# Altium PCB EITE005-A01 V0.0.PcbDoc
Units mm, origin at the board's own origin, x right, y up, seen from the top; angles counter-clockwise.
Board outline 14.16 x 11.86 mm, 4 copper layers (TopLayer, Signal Layer 1, Signal Layer 2, BottomLayer), stack 0.7 mm thick; 45 components, 30 nets, 145 pads, 56 vias.
Unrouted connection lines stored in the file: 1.
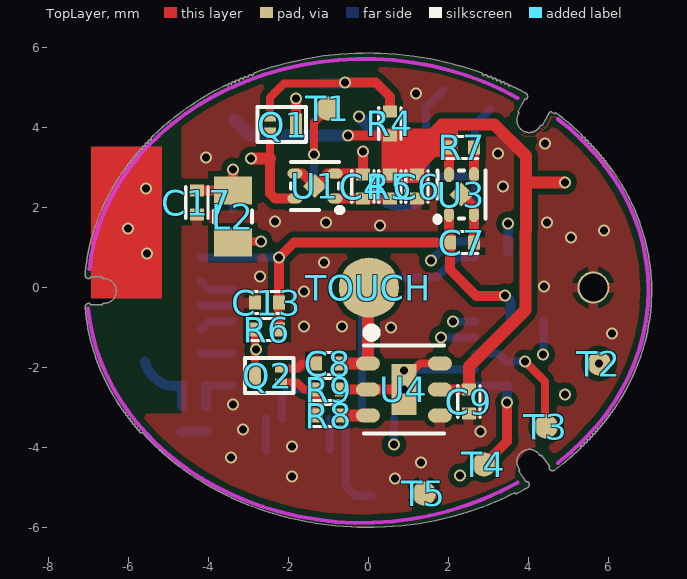
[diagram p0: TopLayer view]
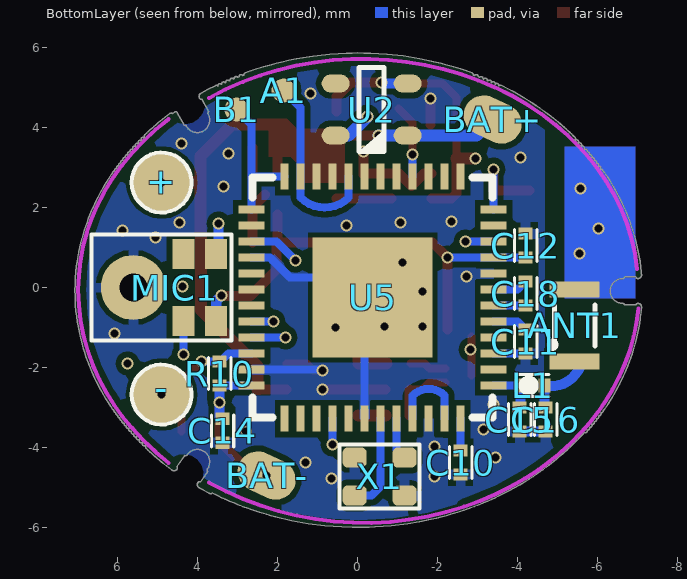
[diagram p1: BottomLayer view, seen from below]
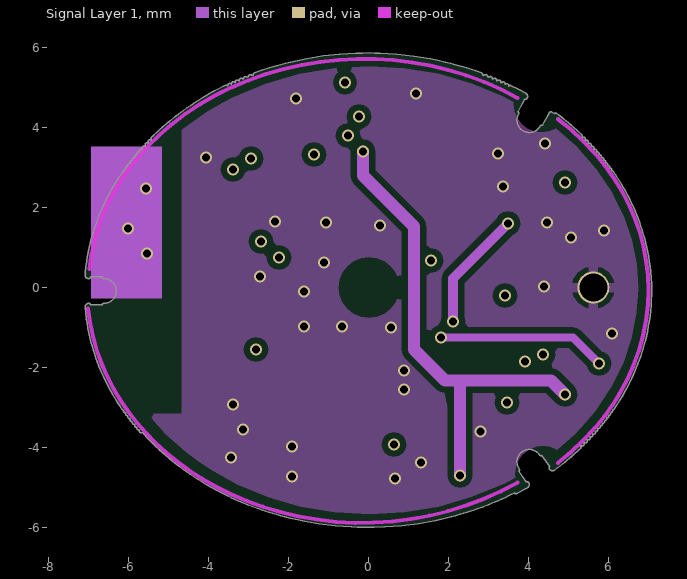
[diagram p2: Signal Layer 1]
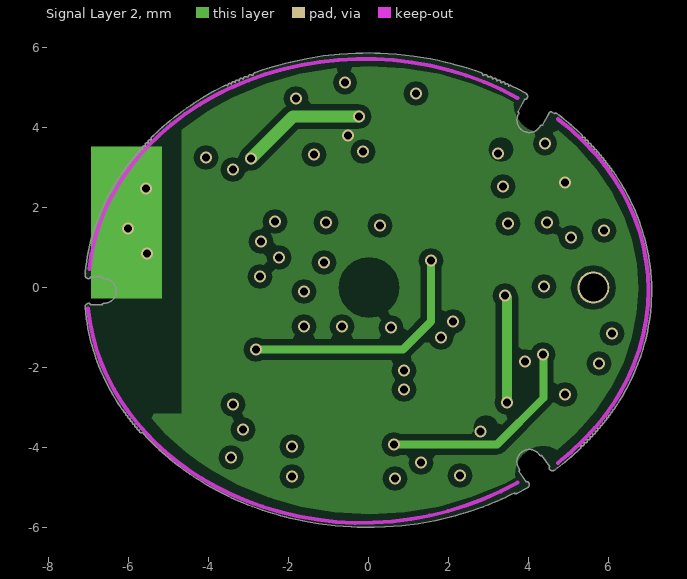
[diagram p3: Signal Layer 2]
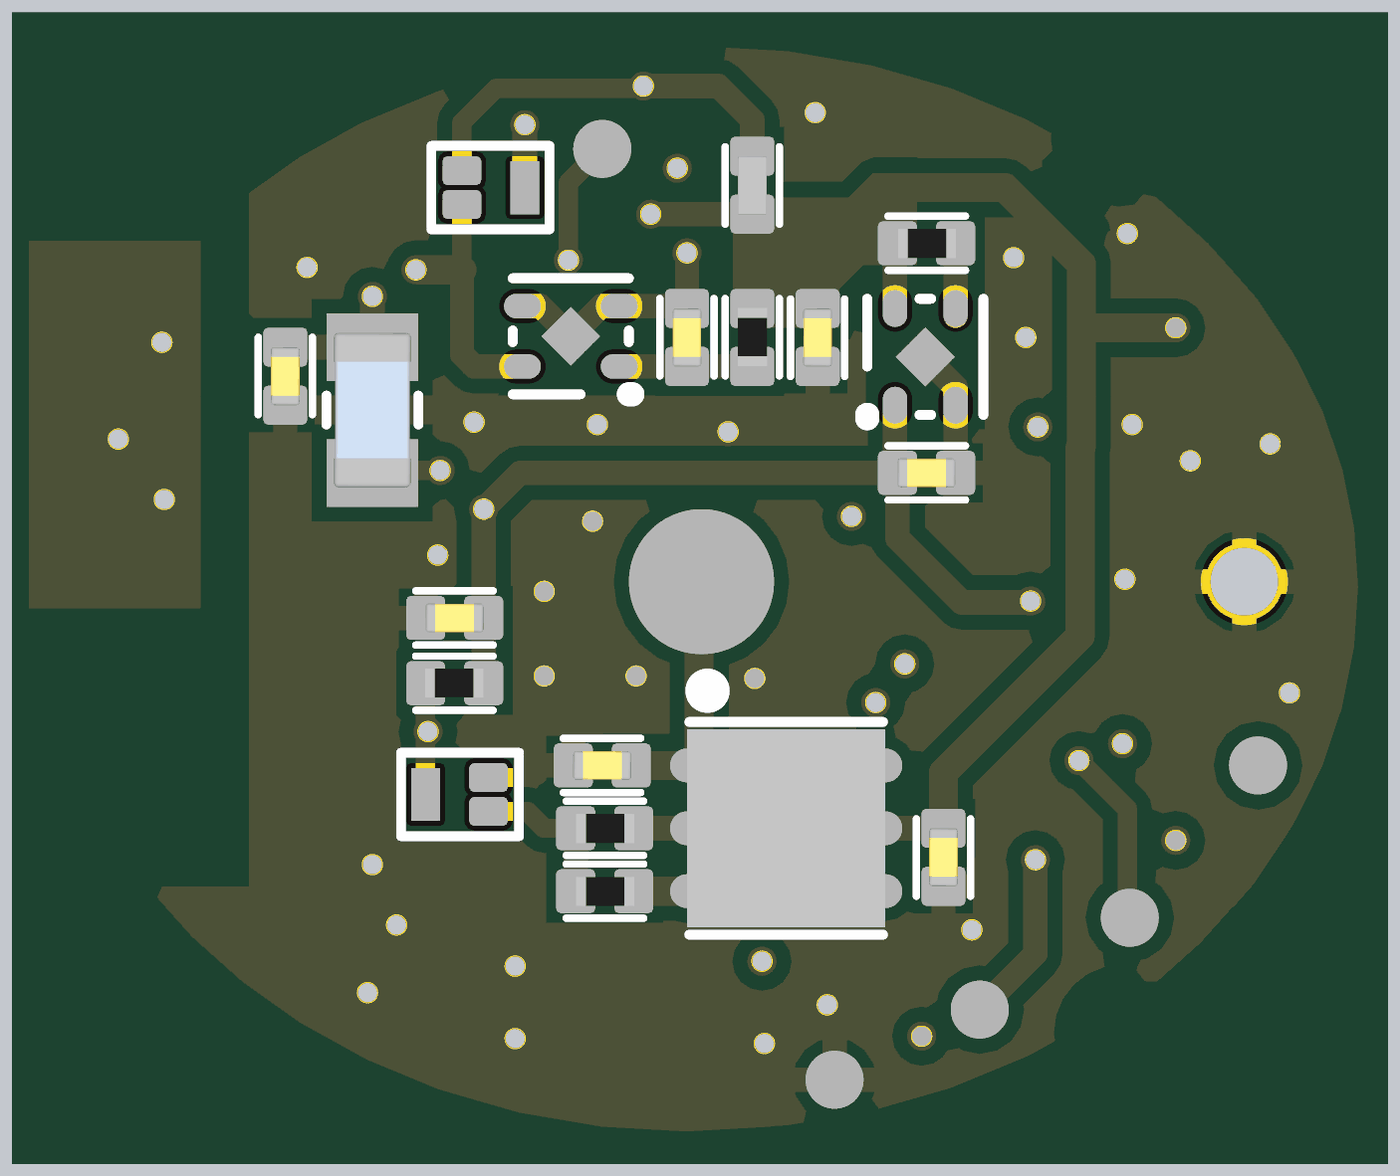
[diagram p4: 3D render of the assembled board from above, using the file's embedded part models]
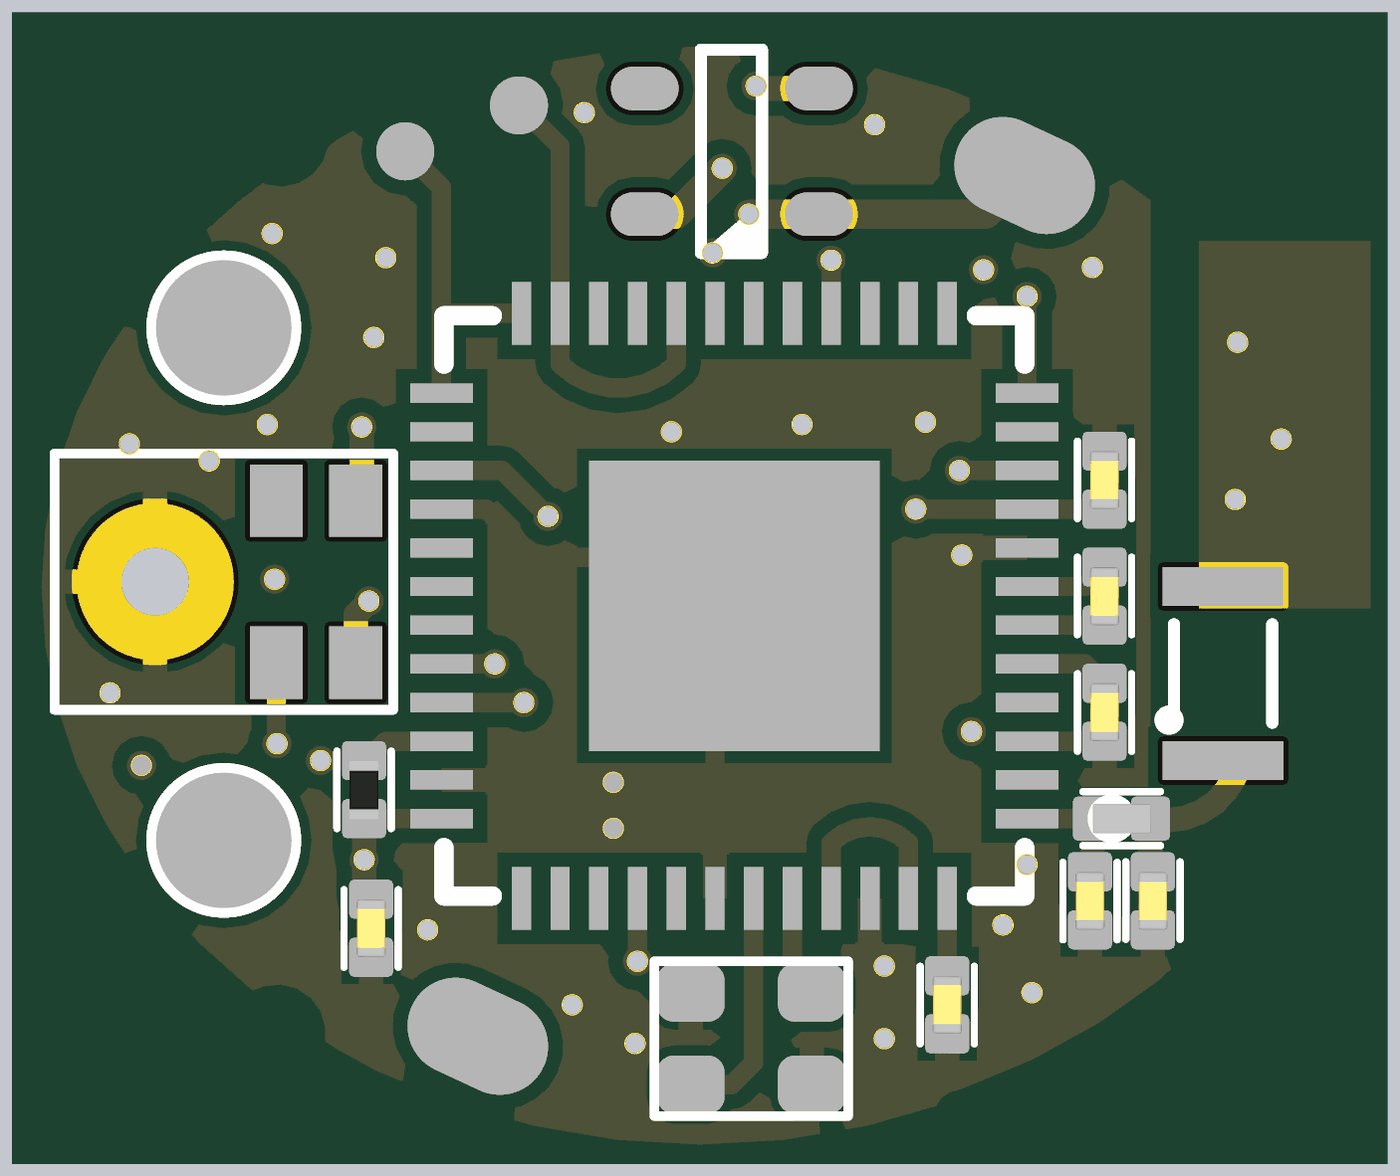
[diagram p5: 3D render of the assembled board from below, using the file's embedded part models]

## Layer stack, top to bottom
TopSolder: solder mask 0.05, Solder Resist, Dk 3.5
TopLayer: signal copper 0.05
Dielectric1: core 0.147, FR-4, Dk 4.2
Signal Layer 1: signal copper 0.036
Dielectric 3: prepreg 0.127, Dk 4.2
Signal Layer 2: signal copper 0.036
Dielectric 2: core 0.254, Dk 4.2
BottomLayer: signal copper 0.05
BottomSolder: solder mask 0.05, Solder Resist, Dk 3.5

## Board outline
799 vertices, not listed, extent -7.098,-5.996 7.067,5.863

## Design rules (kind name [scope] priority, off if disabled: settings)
Clearance [All] p1: gap=0.15 ignorepadtopadclearanceinfootprint=FALSE except(0: Arc-Hole Track-Hole SMDPad-Hole THPad-Hole Via-Hole Fill-Hole Poly-Hole Region-Hole Text-Hole)
FabricationTestPointUsage TestPointUsage [All] p1: valid=0 allowmultiple=FALSE
FabricationTestpoint Testpoint [All] p1: side=3 testpointundercomponent=TRUE minsize=1.016 maxsize=2.54 preferedsize=1.524 minholesize=0.508 maxholesize=1.016 preferedholesize=0.813 testpointgrid=0.025 allowsidetop=TRUE allowsidebottom=TRUE usegrid=TRUE gridtolerance=0
PlaneClearance [All] p1: clearance=0.127
PolygonConnect PolygonConnect_1 [IsVia] p1: connectstyle=Direct reliefconductorwidth=0.254 reliefentries=4 polygonreliefangle="90 Angle" airgapwidth=0.254
PolygonConnect [All vs (InPadClass('All Pads'))] p2: connectstyle=Relief reliefconductorwidth=0.25 reliefentries=4 polygonreliefangle="90 Angle" airgapwidth=0.127
RoutingVias [All] p1: holewidth=0.711 width=1.27 viastyle="Through Hole" minholewidth=0.1 minwidth=1.27 maxholewidth=0.711 maxwidth=1.27
SilkToSolderMaskClearance SilkscreenOverComponentPads [IsPad] p1: minsilkscreentomaskgap=0.254 clearancetoexposedcopper=TRUE
SolderMaskExpansion [All] p1: expansion=0
Width [All] p1: maxlimit=2 minlimit=0.1 preferedwidth=0.254 toplayer_prefwidth=0.15 bottomlayer_prefwidth=0.15 minimp=50.000000 maximp=50.000000 favimp=50.000000
26 further rules are at their usual default settings.

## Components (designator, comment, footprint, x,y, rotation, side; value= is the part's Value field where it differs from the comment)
+ "" PAD_1#1 5.1,2.825 r180 bottom locked
- "" PAD_1#2 4.9,-2.675 r180 bottom
A1 "PAD" PAD0608 1.85,4.925 r180 bottom
ANT1 "ANT_SMD" ANT2012_2.4G_1 -5.425,-0.95 r90 bottom
B1 "PAD" PAD0608 3.025,4.45 r180 bottom
BAT+ "" PAD_1#3 -3.375,4.2 r0 bottom
BAT- "" PAD_1#3 2.275,-4.7 r0 bottom
C4 "100nF" 0201-C -0.15,2.525 r90 top
C6 "4.7uF" 0201-C 1.2,2.525 r270 top
C7 "4.7uF" 0201-C 2.325,1.125 r0 top
C8 "1-50pF" 0201-C -1.025,-1.9 r180 top
C9 "0.1uF" 0201-C 2.5,-2.85 r270 top
C10 "2.2uF" 0201-C -2.575,-4.375 r270 bottom
C11 "1uF" 0201-C -4.2,-1.35 r270 bottom
C12 "4.7uF" 0201-C -4.2,1.05 r90 bottom
C13 "100pF" 0201-C -2.55,-0.375 r180 top
C14 "1uF" 0201-C 3.377,-3.583 r270 bottom
C15 "1pF" 0201-C -4.05,-3.3 r270 bottom
C16 "1pF" 0201-C -4.7,-3.3 r90 bottom
C17 "4.7uF" 0201-C -4.3,2.125 r90 top
C18 "1uF" 0201-C -4.2,-0.15 r90 bottom
L1 "2.2uH" 0201 -4.075,-2.45 r180 bottom
L2 "2.2uH" L_0603 -3.4,1.775 r270 top
MIC1 "SPH0641LM4H-1" SPH0641LM4H-1 5.609,0 r270 bottom locked
Q1 "RV2C002UN" DFN1006 -1.825,4.075 r270 top
Q2 "RV2C002UN" DFN1006 -2.85,-2.2 r90 top
R4 "470K" 0201 0.525,4.4 r270 top
R5 "100R" 0201-R 0.525,2.525 r90 top
R6 "100K" 0201-R -2.55,-1.05 r180 top
R7 "10K" 0201-R 2.325,3.5 r0 top
R8 "100K" 0201-R -1,-3.2 r0 top
R9 "100K" 0201-R -1,-2.55 r0 top
R10 "100K" 0201-R 3.45,-2.15 r270 bottom
T1 "" PAD06 -1.025,4.475 r0 top
T2 "" PAD06 5.75,-1.9 r270 top
T3 "" PAD06 4.425,-3.475 r270 top
T4 "" PAD06 2.875,-4.425 r270 top
T5 "" PAD06 1.375,-5.15 r270 top
TOUCH "" PAD_1#2 0,0 r90 top
U1 "XB6042Q2SV" UTDFN-4L_1 -0.85,2.225 r90 top
U2 "MRX1518H" SON-4 -0.35,4.45 r90 bottom
U3 "SGM2036-1V3" UTDFN-4L_1 2,1.825 r0 top
U4 "TTP233D" DNF-6 0.875,-2.55 r0 top
U5 "RSL10" "QFN-48 RSL10" -0.375,-0.25 r0 bottom locked
X1 "48MHZ" SMDP4P_2016 -0.55,-4.725 r180 bottom

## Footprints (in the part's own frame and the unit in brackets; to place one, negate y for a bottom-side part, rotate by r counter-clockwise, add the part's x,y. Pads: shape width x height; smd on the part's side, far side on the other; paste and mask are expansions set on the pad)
0201 [mil]
  rect 12x14 smd paste+1.97 mask+1.97: 1(0,0) 2(23.62,0)
  silkscreen extent -4,-11 28,11, body extent 0,-6 24,6, height 12
0201-C [mil]
  rect 12x14 smd paste+1.97 mask+1.97: 1(-11.81,0) 2(11.81,0)
  silkscreen extent -16,-11 16,11, body extent -12,-6 12,6, height 12
0201-R [mil]
  rect 12x14 smd paste+1.97 mask+1.97: 1(-11.81,0) 2(11.81,0)
  silkscreen extent -16,-11 16,11, body extent -12,-6 12,6, height 7
ANT2012_2.4G_1 [mm]
  rect 0.4x1.25 smd mask+0.05: 1(-0.9,0) 2(0.9,0)
  silkscreen extent -0.51,-0.51 0.51,0.56
DFN1006 [mm]
  rect 0.55x0.3 smd paste+0 mask+0.05: D(0,0)
  rect 0.2x0.3 smd paste+0.05 mask+0.1: G(-0.175,-0.65) S(0.175,-0.65)
  silkscreen extent -0.43,-0.97 0.43,0.25
DNF-6 [mm]
  oval 0.6x0.35 smd: 1(-0.9,0.65) 2(-0.9,0) 3(-0.9,-0.65) 4(0.9,-0.65) 5(0.9,0) 6(0.9,0.65)
  rect 0.635x1.27 smd: 7(0,0)
  silkscreen extent -1,-1.1 1,1.52, body extent -1.02,-1.03 1.03,1.02, height 0.8
L_0603 [mm]
  rect 0.7x0.95 smd: 1(-0.65,0) 2(0.65,0)
  silkscreen extent -0.15,-0.48 0.15,0.48, body extent -0.8,-0.4 0.8,0.4, height 0.8
PAD06 [mm]
  round 0.6 smd: 0(0,0)
PAD0608 [mm]
  round 0.6 smd: 0(0,0)
PAD_1#1 [mm]
  round 1.5 smd: 0(0.2,-0.2)
PAD_1#2 [mm]
  round 1.5 smd: 0(0,0)
PAD_1#3 [mm]
  oval 1.5x1 smd rot 155: 0(0,0)
"QFN-48 RSL10" [mm]
  rect 0.65x0.2 smd: 1(-3.025,2.2) 2(-3.025,1.8) 3(-3.025,1.4) 4(-3.025,1) 5(-3.025,0.6) 6(-3.025,0.2) 7(-3.025,-0.2) 8(-3.025,-0.6) 9(-3.025,-1) 10(-3.025,-1.4) 11(-3.025,-1.8) 12(-3.025,-2.2) 25(3.025,-2.2) 26(3.025,-1.8) 27(3.025,-1.4) 28(3.025,-1) 29(3.025,-0.6) 30(3.025,-0.2) 31(3.025,0.2) 32(3.025,0.6) 33(3.025,1) 34(3.025,1.4) 35(3.025,1.8) 36(3.025,2.2)
  rect 0.2x0.65 smd: 13(-2.2,-3.025) 14(-1.8,-3.025) 15(-1.4,-3.025) 16(-1,-3.025) 17(-0.6,-3.025) 18(-0.2,-3.025) 19(0.2,-3.025) 20(0.6,-3.025) 21(1,-3.025) 22(1.4,-3.025) 23(1.8,-3.025) 24(2.2,-3.025) 37(2.2,3.025) 38(1.8,3.025) 39(1.4,3.025) 40(1,3.025) 41(0.6,3.025) 42(0.2,3.025) 43(-0.2,3.025) 44(-0.6,3.025) 45(-1,3.025) 46(-1.4,3.025) 47(-1.8,3.025) 48(-2.2,3.025)
  rect 3x3 smd: 49(0,0)
  silkscreen extent -4.02,-3 3,3, body extent -3,-3 3,3, height 1
SMDP4P_2016 [mm]
  rrect50% 0.6x0.5 smd paste+0.05: 1(-0.625,-0.475) 2(0.625,-0.475) 3(0.625,0.475) 4(-0.625,0.475)
  silkscreen extent -1,-0.8 1,0.8
SON-4 [mm]
  oval 0.45x0.7 smd mask+0.051: 1(-0.65,-0.9) 2(0.65,-0.9) 3(0.65,0.9) 4(-0.65,0.9)
  silkscreen extent -1.05,-0.31 1.05,0.32
SPH0641LM4H-1 [mm]
  rect 0.75x0.55 smd mask+0.05: 1(-0.837,2.074) 2(-0.838,1.252) 4(0.838,1.252) 5(0.837,2.074)
  round 1.625 / inner round 0.8 / far side round 0.8 hole 0.7 mask+0.05: 3(0,0)
  silkscreen extent -1.33,-1.04 1.33,2.46
UTDFN-4L_1 [mil]
  oval 10x15 smd mask+1.97: 1(0,0) 2(24.61,0) 3(24.61,39.37) 4(0,39.37)
  rect 17x17 smd rot 45: 5(12.3,19.69)
  silkscreen extent -11,-5 36,43

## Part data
+ - BAT+ BAT- T1 T2 T3 T4 T5 TOUCH: library part PAD
C4 C6 C7 C8 C9 C10 C11 C12 C13 C14 C15 C16 C17 C18: library part CAP, "Capacitor"
L1 L2: library part L
MIC1: library part MIC
Q1 Q2: library part MOS-N
R4 R5 R6 R7 R8 R9 R10: library part Res1, "Resistor"
U1: library part XB6042
U3: library part SGM2036
U5: "RSL10 QFN-48"
X1: library part XT

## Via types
v1: diameter 0.3, hole 0.2, TopLayer to BottomLayer, tented both sides, 56 vias

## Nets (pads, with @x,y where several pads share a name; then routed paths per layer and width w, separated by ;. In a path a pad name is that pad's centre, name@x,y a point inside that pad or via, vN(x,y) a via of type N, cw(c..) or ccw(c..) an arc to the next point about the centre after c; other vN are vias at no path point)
1V85: C7.1 C12.1 C13.1 C14.1 MIC1.5 R6.1 R10.2 T4.0 U3.1 U5.9 U5.36 | length 18
  TopLayer w0.25: R6.1 C13.1 v1(-2.25,0.75) -1.875,1.125 C7.1@2,1.125 ; U3.1 C7.1@2,1.125 ; C7.1 C7.1@2,1.125 ; T4.0 3.45,-3.85 v1(3.45,-2.875)
  TopLayer w0.254: C7.1 2.025,0.45 2.69,-0.215 v1@3.425,-0.215
  Signal Layer 2 w0.254: v1(3.4,-0.2) 3.45,-0.25 v1(3.45,-2.875)
  BottomLayer w0.2: C12.1 U5.9 v1(-2.25,0.75) ; U5.36 R10.2
  BottomLayer w0.254: v1(3.4,-0.2) 3.535,-0.335 MIC1.5 ; C14.1@3.45,-3.275 v1(3.45,-2.875) R10.2
AGND: Q1.S U1.4 U2.4 | length 6.8
  TopLayer w0.2: -2.475,3.225 Q1.S
  TopLayer w0.25: -2.475,3.225 -2.475,2.35 -2.35,2.225 U1.4
  TopLayer w0.3: v1(-2.95,3.225) -2.475,3.225
  Signal Layer 2 w0.3: v1(-2.95,3.225) -1.9,4.275 v1(-0.25,4.275)
  BottomLayer w0.3: v1(-0.25,4.275) 0.225,3.8 U2.4
GND: ANT1.2 C6.2 C7.2 C8.2 C9.2 C10.2 C11.2 C12.2 C13.2 C14.2 C15.2 C16.1 C17.1 MIC1.3 Q1.D Q2.S R9.2 T5.0 U3.2 U3.5 U4.2 U4.4 U4.6 U5.3 U5.8 U5.28 U5.35 U5.42 U5.46 U5.49 X1.2 X1.4 | length 14.9
  TopLayer w0.2: Q2.S -1.8,-2.025 -1.7,-1.925 -1.675,-1.9 C8.2 ; v1(0.875,-2.075) 1.1,-2.075 1.275,-1.9 U4.6
  TopLayer w0.254: Q1.D v1(-1.825,4.725) ; R9.2 U4.2 v1(0.875,-2.55) ; U3.5 2.625,2.013 U3.2 C7.2
  BottomLayer w0.2: C11.2 U5.3 ; U5.49 0.125,0.25 1.691,0.25 2.191,0.75 U5.28 ; U5.42 U5.49@-0.175,-0.45 ; v1@0.9,-2.05 U5.35
  BottomLayer w0.254: C16.1 C15.2
  other v1: 0.65,-4.775 -1.925,-4.725 1.3,-4.375 -3.45,-4.25 -1.925,-3.975 2.793,-3.6 -3.15,-3.55 -3.4,-2.925 6.075,-1.15 0.55,-1 -1.625,-0.975 -0.675,-0.975 -1.625,-0.1 4.375,0.025 -2.725,0.275 -1.125,0.625 5.05,1.25 5.875,1.425 0.275,1.55 -1.075,1.625 4.45,1.625 -2.35,1.65 3.35,2.525 -4.075,3.25 3.225,3.35 4.4,3.6 1.175,4.85
JTCK: T2.0 U5.33 | length 5.1
  Signal Layer 1 w0.2: v1(1.8,-1.25) 5.1,-1.25 v1(5.75,-1.9)
  BottomLayer w0.2: v1(1.8,-1.25) U5.33
JTMS: R10.1 T3.0 U5.34 | length 3.3
  TopLayer w0.2: v1(3.9,-1.85) 4.4,-2.35 T3.0@4.4,-3.6
  BottomLayer w0.2: U5.34 3.225,-1.65 3.425,-1.85 R10.1 v1(3.9,-1.85)
KEY: Q2.D R6.2 U5.27 | length 8.5
  TopLayer w0.2: Q2.D R6.2@-2.85,-1.225
  Signal Layer 2 w0.2: v1(-2.825,-1.55) 0.85,-1.55 1.55,-0.85 v1(1.55,0.675)
  BottomLayer w0.2: v1(1.55,0.675) 2.025,1.15 U5.27
MIC_CLK: MIC1.4 U5.40 | length 6.8
  Signal Layer 2 w0.2: v1(0.625,-3.925) 3.2,-3.925 4.357,-2.768 v1@4.357,-1.675
  BottomLayer w0.2: v1(0.625,-3.925) U5.40 ; v1@4.357,-1.675 MIC1.4
  other v1: 4.35,-1.675
MIC_DATA: MIC1.1 U5.32 | length 4.3
  Signal Layer 1 w0.254: v1(2.1,-0.85) 2.1,0.225 v1(3.475,1.6)
  BottomLayer w0.2: v1(2.1,-0.85) U5.32
  BottomLayer w0.254: MIC1.1@3.475,0.898 v1(3.475,1.6)
Net-_0: -.0 BAT-.0 C4.2 U1.2 U1.3 U1.5 | length 14.6
  TopLayer w0.25: U1.3 -1.662,2.85 U1.5 -1.038,2.85 U1.2 C4.2@-0.175,2.85 ; C4.2 v1(-0.15,3.4)
  Signal Layer 1 w0.3: v1(-0.15,3.4) -0.15,2.8 1.125,1.525 1.125,-1.55 1.9,-2.325 2.275,-2.325 ; v1(2.275,-4.7) 2.275,-2.325 ; v1(4.9,-2.675) 4.55,-2.325 2.275,-2.325
NetANT1_1: ANT1.1 C16.2 L1.2 | length 1.7
  BottomLayer w0.254: ANT1.1@-5.6,-1.85 ccw(c-4.84,-1.69) L1.2@-4.68,-2.45 ; C16.2@-4.675,-2.975 L1.2
NetC4_1: C4.1 R5.1 U1.1 | length 1.4
  TopLayer w0.25: U1.1 C4.1
  TopLayer w0.254: C4.1 R5.1
NetC8_1: C8.1 TOUCH.0 U4.1 | length 2.6
  TopLayer w0.3: C8.1 U4.1 TOUCH.0@-0.025,-0.025
NetC10_1: C10.1 U5.48 | length 0.8
  BottomLayer w0.2: C10.1 U5.48
NetC15_1: C15.1 L1.1 U5.1 | length 1.2
  BottomLayer w0.2: L1.1 U5.1
  BottomLayer w0.254: C15.1@-4.075,-2.975 L1.1
NetC17_2: C17.2 L2.1 U5.12 | length 2.4
  TopLayer w0.254: C17.2 L2.1 v1(-3.4,2.95)
  BottomLayer w0.2: U5.12 v1(-3.4,2.95)
NetC18_1: C18.1 U5.6 | length 0.8
  BottomLayer w0.2: C18.1 U5.6
NetC18_2: C18.2 U5.7 | length 0.9
  BottomLayer w0.2: C18.2 -4,-0.05 U5.7
NetL2_2: L2.2 U5.10 | length 1.4
  TopLayer w0.2: L2.2@-3.375,1.15 v1(-2.7,1.15)
  BottomLayer w0.2: U5.10 v1(-2.7,1.15)
NetQ1_G: Q1.G R4.1 U2.2 | length 4.8
  TopLayer w0.2: Q1.G -2.475,4.75 -2.125,5.1 -0.625,5.1 v1(-0.6,5.125)
  TopLayer w0.254: v1(-0.6,5.125) 0.175,5.125 0.525,4.775 R4.1
  BottomLayer w0.254: U2.2 -0.625,5.1 v1(-0.6,5.125)
NetQ2_G: Q2.G R8.1 R9.1 | length 1.6
  TopLayer w0.2: Q2.G -1.8,-2.375 -1.625,-2.55 R9.1
  TopLayer w0.254: R8.1 R9.1
NetR7_2: R7.2 U3.3 | length 0.8
  TopLayer w0.25: U3.3@2.625,2.75 U3.3 R7.2
NetR8_2: R8.2 U4.3 | length 0.7
  TopLayer w0.3: R8.2 U4.3
NetU5_45: U5.45 U5.47 | length 2
  BottomLayer w0.2: U5.47 -2.175,-2.7 cw(c-1.775,-3.1) -1.375,-2.7 U5.45
NRST: T1.0 U5.16 | length 1.8
  TopLayer w0.2: v1(-1.375,3.325) -1.375,4.125 T1.0
  BottomLayer w0.2: U5.16 v1(-1.375,3.325)
SPEAKER+: A1.0 U5.20 U5.23 | length 4.7
  BottomLayer w0.2: U5.20 0.225,2.25 ccw(c0.825,2.85) 1.425,2.25 U5.23 1.425,4.5 A1.0
SPEAKER-: B1.0 U5.24 U5.25 | length 3.5
  BottomLayer w0.2: U5.24 2.65,2.775 ; U5.25 2.65,2.775 ; B1.0 2.65,4.075 2.65,2.775
VCC: +.0 BAT+.0 C6.1 C9.1 R4.2 R5.2 R7.1 U2.1 U3.4 U4.5 | length 15.6
  TopLayer w0.25: U3.4 R7.1@2,3.5 ; R7.1 R7.1@2.025,3.525
  TopLayer w0.254: v1(-0.525,3.8) R4.2 ; U4.5 C9.1
  TopLayer w0.3: R5.2 C6.1 ; 2.223,4.075 3.136,4.075 3.925,3.286 3.925,2.625 ; C9.1 2.5,-1.975 3.912,-0.563 3.912,1.388 3.925,1.401 3.925,2.625 ; v1(4.9,2.625) 3.925,2.625
  BottomLayer w0.3: BAT+.0 -2.975,3.8 U2.1 v1(-0.525,3.8)
VDDA: C11.1 U5.5 | length 0.9
  BottomLayer w0.2: C11.1 -4,-0.85 U5.5
XTAL48N: U5.43 X1.1 | length 2.4
  BottomLayer w0.2: U5.43 -0.575,-4.975 -0.35,-5.2 X1.1
XTAL48P: U5.44 X1.3 | length 0.8
  BottomLayer w0.2: X1.3@-0.975,-4.05 U5.44
pads on no net: MIC1.2 U2.3 U4.7 U5.2 U5.4 U5.11 U5.13 U5.14 U5.15 U5.17 U5.18 U5.19 U5.21 U5.22 U5.26 U5.29 U5.30 U5.31 U5.37 U5.38 U5.39 U5.41
copper on no net:
  other v1: -5.55,0.85 -6.025,1.475 -5.575,2.475

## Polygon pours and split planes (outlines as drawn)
GND on Signal Layer 1 "Top Layer-No Net" (solid, remove dead copper, pour order 6): -6.202,-2.528 cw(c-1.704,0.024) -6.848,-0.507 ccw(c-6.923,-0.012) -6.861,0.484 cw(c-1.886,-0.046) -6.298,2.313 cw(c-1.359,-0.342) -5.657,3.26 cw(c-0.89,-0.734) -4.819,4.087 cw(c-0.467,-1.256) -3.725,4.816 cw(c0.01,-2.311) 2.105,5.458 cw(c0.153,-1.851) 3.843,4.753 ccw(c4.315,4.585) 4.674,4.237 cw(c0.862,-0.788) 5.581,3.396 cw(c1.343,-0.366) 6.288,2.404 cw(c1.97,-0.043) 6.932,-0.023 cw(c1.803,-0.003) 6.218,-2.614 cw(c1.274,0.265) 5.62,-3.456 cw(c0.823,0.65) 4.709,-4.327 4.704,-4.315 ccw(c4.347,-4.665) 3.888,-4.863 cw(c0.017,2.075) -2.487,-5.465 cw(c-0.206,1.444) -4.348,-4.538 cw(c-0.671,0.762) -5.402,-3.623 cw(c-1.154,0.32)
VCC on Signal Layer 2 "Top Layer-No Net" (solid, remove dead copper, pour order 5): -6.202,-2.528 cw(c-1.704,0.024) -6.848,-0.507 ccw(c-6.923,-0.012) -6.861,0.484 cw(c-1.886,-0.046) -6.298,2.313 cw(c-1.359,-0.342) -5.657,3.26 cw(c-0.89,-0.734) -4.819,4.087 cw(c-0.467,-1.256) -3.725,4.816 cw(c0.01,-2.311) 2.105,5.458 cw(c0.153,-1.851) 3.843,4.753 ccw(c4.315,4.585) 4.674,4.237 cw(c0.862,-0.788) 5.581,3.396 cw(c1.343,-0.366) 6.288,2.404 cw(c1.97,-0.043) 6.932,-0.023 cw(c1.803,-0.003) 6.218,-2.614 cw(c1.274,0.265) 5.62,-3.456 cw(c0.823,0.65) 4.709,-4.327 4.704,-4.315 ccw(c4.347,-4.665) 3.888,-4.863 cw(c0.017,2.075) -2.487,-5.465 cw(c-0.206,1.444) -4.348,-4.538 cw(c-0.671,0.762) -5.402,-3.623 cw(c-1.154,0.32)
GND on BottomLayer "Top Layer-No Net" (solid, remove dead copper, pour order 8): -6.202,-2.528 cw(c-1.704,0.024) -6.848,-0.507 ccw(c-6.923,-0.012) -6.861,0.484 cw(c-1.886,-0.046) -6.298,2.313 cw(c-1.359,-0.342) -5.657,3.26 cw(c-0.89,-0.734) -4.819,4.087 cw(c-0.467,-1.256) -3.725,4.816 cw(c0.01,-2.311) 2.105,5.458 cw(c0.153,-1.851) 3.843,4.753 ccw(c4.315,4.585) 4.674,4.237 cw(c0.862,-0.788) 5.581,3.396 cw(c1.343,-0.366) 6.288,2.404 cw(c1.97,-0.043) 6.932,-0.023 cw(c1.803,-0.003) 6.218,-2.614 cw(c1.274,0.265) 5.62,-3.456 cw(c0.823,0.65) 4.709,-4.327 4.704,-4.315 ccw(c4.347,-4.665) 3.888,-4.863 cw(c0.017,2.075) -2.487,-5.465 cw(c-0.206,1.444) -4.348,-4.538 cw(c-0.671,0.762) -5.402,-3.623 cw(c-1.154,0.32)
no net on Mechanical1 (solid, remove dead copper): 3.916,4.777
no net on TopLayer (solid, pour order 12): 3.812,3.822 ccw(c4.008,4.184) 4.352,3.959 4.428,4.012 4.567,4.268 4.656,4.252 4.756,4.175 4.869,4.083 4.87,4.083 4.871,4.083 4.977,3.993 4.978,3.992 5.073,3.909 5.074,3.908 5.164,3.826 5.226,3.768 5.256,3.683 5.26,3.679 5.263,3.675 5.307,3.65 5.333,3.606 5.335,3.604 5.337,3.602 5.38,3.576 5.405,3.532 5.407,3.53 5.409,3.528 5.453,3.501 5.52,3.43 5.592,3.356 5.616,3.316 5.65,3.293 5.677,3.245 5.713,3.222 5.767,3.159 5.82,3.093 5.875,3.024 5.922,2.963 5.969,2.899 6.035,2.824 6.08,2.758 6.08,2.759 6.08,2.758 6.035,2.824 5.969,2.899 5.922,2.963 5.875,3.024 5.82,3.093 5.767,3.159 5.713,3.222 5.677,3.245 5.65,3.293 5.616,3.316 5.592,3.356 5.52,3.43 5.453,3.501 5.409,3.528 5.405,3.532 5.38,3.576 5.337,3.602 5.333,3.606 5.307,3.65 5.264,3.675 5.263,3.675 5.26,3.679 5.256,3.683 5.255,3.683 5.226,3.768 5.164,3.826 5.074,3.908 5.073,3.909 4.978,3.992 4.977,3.993 4.871,4.083 4.87,4.083 4.869,4.083 4.756,4.175 4.656,4.252 4.567,4.268 4.428,4.012
no net on TopLayer (solid, pour order 10): 3.812,3.822 ccw(c4.008,4.184) 4.352,3.959 4.428,4.012 4.567,4.268 4.656,4.252 4.756,4.175 4.869,4.083 4.87,4.083 4.871,4.083 4.977,3.993 4.978,3.992 5.073,3.909 5.074,3.908 5.164,3.826 5.226,3.768 5.256,3.683 5.26,3.679 5.263,3.675 5.307,3.65 5.333,3.606 5.335,3.604 5.337,3.602 5.38,3.576 5.405,3.532 5.407,3.53 5.409,3.528 5.453,3.501 5.52,3.43 5.592,3.356 5.616,3.316 5.65,3.293 5.677,3.245 5.713,3.222 5.767,3.159 5.82,3.093 5.875,3.024 5.922,2.963 5.969,2.899 6.035,2.824 6.08,2.758 6.08,2.759 6.08,2.758 6.035,2.824 5.969,2.899 5.922,2.963 5.875,3.024 5.82,3.093 5.767,3.159 5.713,3.222 5.677,3.245 5.65,3.293 5.616,3.316 5.592,3.356 5.52,3.43 5.453,3.501 5.409,3.528 5.405,3.532 5.38,3.576 5.337,3.602 5.333,3.606 5.307,3.65 5.264,3.675 5.263,3.675 5.26,3.679 5.256,3.683 5.255,3.683 5.226,3.768 5.164,3.826 5.074,3.908 5.073,3.909 4.978,3.992 4.977,3.993 4.871,4.083 4.87,4.083 4.869,4.083 4.756,4.175 4.656,4.252 4.567,4.268 4.428,4.012
GND on TopLayer "Top Layer-No Net" (solid, remove dead copper, pour order 7): 3.861,4.077 4.021,3.935 4.072,3.943 4.196,4.1 3.875,4.347 3.863,4.319
GND on TopLayer "Top Layer-No Net" (solid, remove dead copper, pour order 7): 2.105,5.458 cw(c0.153,-1.849) 3.709,4.826 3.535,4.424 3.521,4.357 3.517,4.003 3.575,3.873 3.852,3.626 3.99,3.584 4.188,3.613 4.299,3.676 4.56,4.007 4.597,4.113 4.588,4.167 4.674,4.237 cw(c0.864,-0.786) 5.581,3.396 cw(c1.344,-0.365) 6.288,2.404 cw(c1.97,-0.042) 6.932,-0.023 cw(c1.803,-0.003) 6.218,-2.614 cw(c1.276,0.264) 5.62,-3.456 cw(c-0.191,1.317) 4.719,-4.378 4.691,-4.338 4.477,-4.031 4.447,-3.998 4.276,-3.852 4.229,-3.824 4.021,-3.741 3.857,-3.761 3.856,-3.762 3.679,-3.89 3.655,-3.911 3.654,-3.912 3.376,-4.207 3.375,-4.207 3.328,-4.325 3.351,-4.411 3.352,-4.411 3.581,-4.811 3.902,-4.725 3.879,-4.639 3.712,-4.35 3.893,-4.159 3.981,-4.095 4.075,-4.132 4.208,-4.245 4.318,-4.403 ccw(c4.291,-4.766) 3.955,-4.904 cw(c0.115,1.912) -2.487,-5.465 cw(c-0.207,1.442) -4.348,-4.538 cw(c-0.671,0.762) -5.402,-3.623 cw(c-1.154,0.32) -6.202,-2.528 cw(c-1.704,0.024) -6.848,-0.507 ccw(c-6.923,-0.012) -6.423,-0.012 ccw(c-6.923,-0.012) -6.861,0.484 cw(c-1.886,-0.046) -6.298,2.313 cw(c-1.359,-0.342) -5.657,3.26 cw(c-0.89,-0.733) -4.819,4.087 cw(c-0.468,-1.255) -3.725,4.816 cw(c0.01,-2.311)

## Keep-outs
KeepOutLayer:
  lines w0.1: -7.024,-0.521 ccw(c-1.88,0.01) -6.378,-2.543 ccw(c-1.33,0.305) -5.578,-3.638 ccw(c-0.847,0.747) -4.524,-4.552 ccw(c-0.382,1.429) -2.663,-5.48 ccw(c-0.159,2.06) 3.712,-4.878 ; -6.987,0.468 cw(c-2.011,-0.063) -6.424,2.297 cw(c-1.484,-0.358) -5.782,3.243 cw(c-1.015,-0.75) -4.944,4.071 cw(c-0.592,-1.272) -3.85,4.8 cw(c-0.116,-2.327) 1.98,5.441 cw(c0.028,-1.867) 3.718,4.736 ; 4.722,-4.389 ccw(c0.837,0.588) 5.634,-3.517 ; 4.728,4.208 cw(c0.916,-0.817) 5.635,3.367 cw(c1.397,-0.395) 6.342,2.375 cw(c2.024,-0.072) 6.986,-0.052 cw(c1.857,-0.032) 6.272,-2.643 cw(c1.328,0.236) 5.674,-3.485

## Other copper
TopLayer:
  rectangle: -6.95,-0.275 -5.175,3.525
  pour cut-out: 0,-0.75 cw(c0,0) -0.75,0 cw(c0,0) 0,0.75 cw(c0,0) 0.75,0 cw(c0,0)
  region net VCC: 0.325,2.625 1.425,2.625 1.425,3.025 1.675,3.275 2.225,3.275 2.225,4.225 1.775,4.225 1.525,3.975 0.325,3.975
  pour cut-out: -4.675,4.35 -4.675,-3.15 -7.35,-3.15 -7.35,2.775
  pour cut-out: -2.79,4.507 -2.79,3.643 -1.571,3.643 -1.571,4.507
  pour cut-out: 1.7,3.075 1.7,1.575 2.925,1.575 2.925,3.075
  pour cut-out: -2.1,1.925 -0.6,1.925 -0.6,3.15 -2.1,3.15
  pour cut-out: -3.104,-1.768 -3.104,-2.632 -1.885,-2.632 -1.885,-1.768
Signal Layer 1:
  rectangle: -6.95,-0.275 -5.175,3.525
  pour cut-out: 0,-0.75 cw(c0,0) -0.75,0 cw(c0,0) 0,0.75 cw(c0,0) 0.75,0 cw(c0,0)
  pour cut-out: -4.675,4.35 -4.675,-3.15 -7.35,-3.15 -7.35,2.775
Signal Layer 2:
  rectangle: -6.95,-0.275 -5.175,3.525
  pour cut-out: 0,-0.75 cw(c0,0) -0.75,0 cw(c0,0) 0,0.75 cw(c0,0) 0.75,0 cw(c0,0)
  pour cut-out: -4.675,4.35 -4.675,-3.15 -7.35,-3.15 -7.35,2.775
BottomLayer:
  rectangle: -6.95,-0.275 -5.175,3.525
  pour cut-out: 0,-0.75 cw(c0,0) -0.75,0 cw(c0,0) 0,0.75 cw(c0,0) 0.75,0 cw(c0,0)
  pour cut-out: -4.675,4.35 -4.675,-3.15 -7.35,-3.15 -7.35,2.775

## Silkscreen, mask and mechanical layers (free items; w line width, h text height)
BottomOverlay:
  circle w0.1: c4.9,-2.675 r0.75
  circle w0.1: c4.9,2.625 r0.75
Mechanical1:
  drawing of 496 lines, arcs and shapes, not listed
